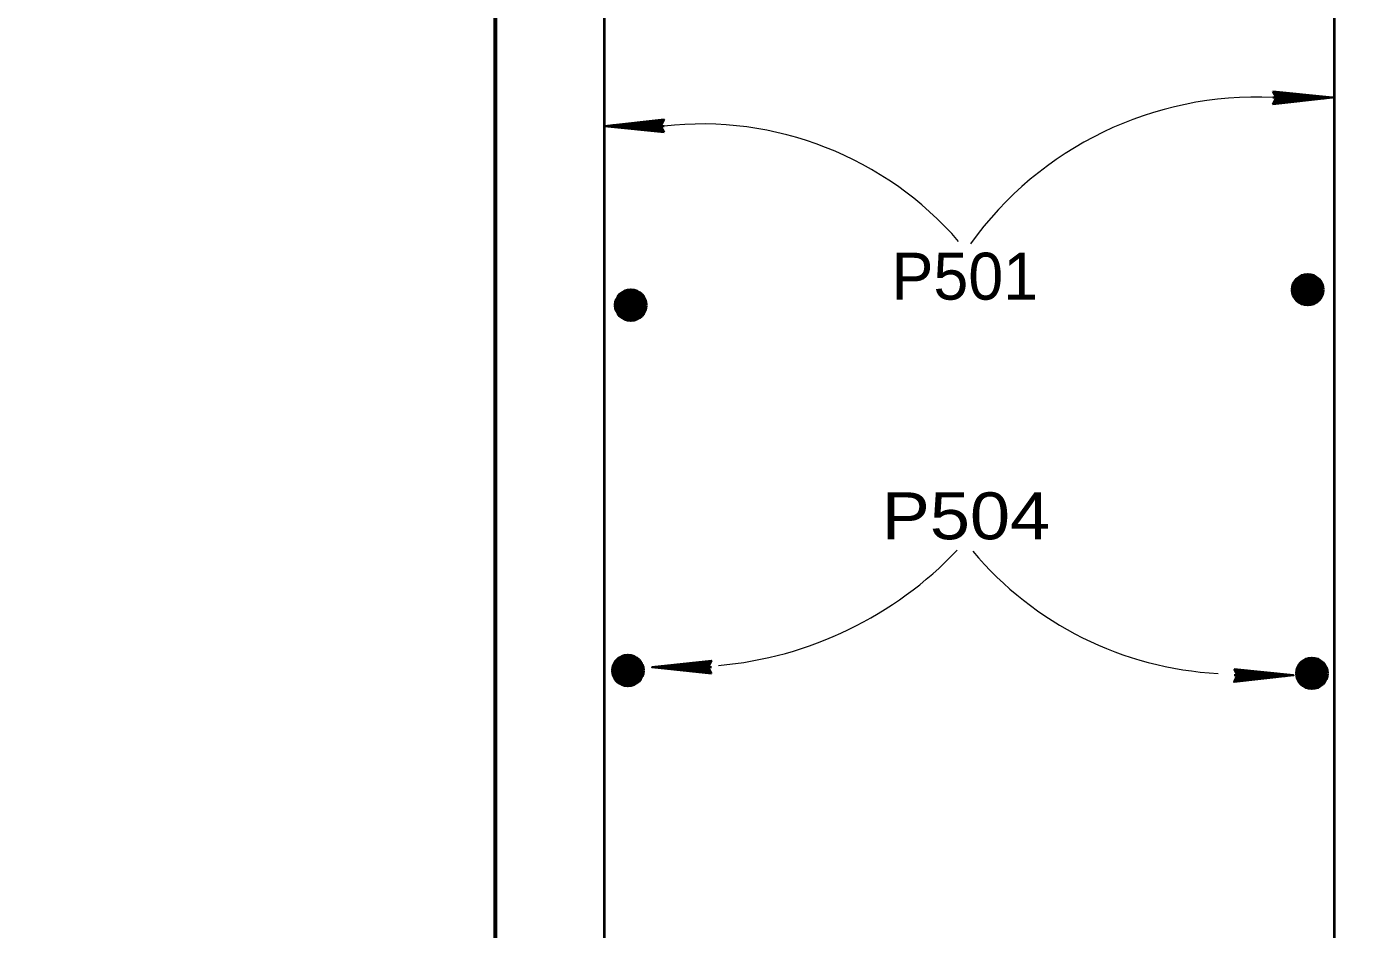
# Model space of a CAD drawing. Extents: x 3.64 to 6.84, y -0.8 to 1.19.
# Drawn here: x 5.0189 to 5.2545, y 0.0313 to 0.1917 of the extents above; entities that cross this region are included whole.
import ezdxf

# ---------------------------------------------------------------- set-up
doc = ezdxf.new("R2010")
doc.units = 0
doc.header["$LTSCALE"] = 0.0033
doc.layers.add('1', color=7, linetype='Continuous', lineweight=40)

msp = doc.modelspace()

# ---------------------------------------------------------------- linework, layer by layer
at = {"layer": '1', "lineweight": 35}
for p, q in [((5.240333, 0.179083), (5.250917, 0.179083)), ((5.2405, 0.178417), (5.247833, 0.179167)), ((5.240583, 0.180083), (5.248417, 0.179167)), ((5.240583, 0.180083), (5.248417, 0.179167)), ((5.240583, 0.18), (5.248417, 0.179167)), ((5.240583, 0.179917), (5.248417, 0.179083)), ((5.240583, 0.179917), (5.248417, 0.178917)), ((5.240583, 0.17825), (5.247917, 0.179083)), ((5.240583, 0.178167), (5.247917, 0.178917)), ((5.240583, 0.178), (5.247917, 0.178833)), ((5.131917, 0.175083), (5.124583, 0.17425)), ((5.131917, 0.174917), (5.124583, 0.174167)), ((5.131917, 0.174833), (5.124583, 0.174)), ((5.132, 0.174667), (5.124667, 0.173917)), ((5.132167, 0.174), (5.121583, 0.174)), ((5.131917, 0.173167), (5.124083, 0.174167)), ((5.131917, 0.173167), (5.124083, 0.174)), ((5.131917, 0.173), (5.124083, 0.173917)), ((5.131917, 0.173), (5.124083, 0.173917)), ((5.131917, 0.173083), (5.124083, 0.173917)), ((5.140583, 0.077833), (5.13, 0.077833)), ((5.140333, 0.077), (5.1325, 0.078)), ((5.140333, 0.077), (5.1325, 0.077833)), ((5.140333, 0.076833), (5.1325, 0.07775)), ((5.140333, 0.076833), (5.1325, 0.07775)), ((5.140333, 0.076917), (5.1325, 0.07775)), ((5.140333, 0.078917), (5.133, 0.078083)), ((5.140333, 0.07875), (5.133, 0.078)), ((5.140333, 0.078667), (5.133, 0.077833)), ((5.140417, 0.0785), (5.133083, 0.07775)), ((5.233417, 0.076417), (5.244, 0.076417)), ((5.233583, 0.07575), (5.240917, 0.0765)), ((5.233667, 0.077417), (5.2415, 0.0765)), ((5.233667, 0.077417), (5.2415, 0.0765)), ((5.233667, 0.077333), (5.2415, 0.0765)), ((5.233667, 0.07725), (5.2415, 0.076417)), ((5.233667, 0.07725), (5.2415, 0.07625)), ((5.233667, 0.075583), (5.241, 0.076417)), ((5.233667, 0.0755), (5.241, 0.07625)), ((5.233667, 0.075333), (5.241, 0.076167))]:
    msp.add_line(p, q, dxfattribs=at)
at = {"layer": '1'}
for p, q in [((5.244417, 0.1465), (5.249, 0.144333)), ((5.244667, 0.146083), (5.248583, 0.145333)), ((5.24475, 0.1465), (5.248667, 0.145833)), ((5.24475, 0.146333), (5.248667, 0.145583)), ((5.244833, 0.146833), (5.248667, 0.146167)), ((5.24675, 0.146), (5.248083, 0.147)), ((5.248833, 0.146167), (5.247583, 0.147333)), ((5.124167, 0.14375), (5.12875, 0.141583)), ((5.1245, 0.14375), (5.128417, 0.143083)), ((5.124583, 0.144083), (5.128417, 0.143417)), ((5.1265, 0.14325), (5.127833, 0.14425)), ((5.128583, 0.143417), (5.127333, 0.144583)), ((5.24425, 0.14375), (5.248083, 0.143)), ((5.244333, 0.14425), (5.24825, 0.1435)), ((5.244333, 0.144083), (5.248167, 0.143333)), ((5.244333, 0.143833), (5.248167, 0.143167)), ((5.244417, 0.144667), (5.248333, 0.143917)), ((5.2445, 0.145083), (5.248333, 0.144333)), ((5.2445, 0.144917), (5.248333, 0.144167)), ((5.244583, 0.1455), (5.248417, 0.144833)), ((5.244583, 0.145333), (5.248417, 0.144583)), ((5.244667, 0.145917), (5.248583, 0.145167)), ((5.244667, 0.145667), (5.2485, 0.144917)), ((5.124083, 0.1415), (5.128, 0.14075)), ((5.124083, 0.141333), (5.127917, 0.140583)), ((5.124167, 0.141917), (5.128083, 0.141167)), ((5.12425, 0.142333), (5.128083, 0.141583)), ((5.12425, 0.142167), (5.128083, 0.141417)), ((5.124333, 0.14275), (5.128167, 0.142083)), ((5.124333, 0.142583), (5.128167, 0.141833)), ((5.124417, 0.143333), (5.128333, 0.142583)), ((5.124417, 0.143167), (5.128333, 0.142417)), ((5.124417, 0.142917), (5.12825, 0.142167)), ((5.1245, 0.143583), (5.128417, 0.142833)), ((5.24425, 0.143583), (5.248083, 0.142833)), ((5.248583, 0.143333), (5.244833, 0.142917)), ((5.124, 0.141), (5.127833, 0.14025)), ((5.124, 0.140833), (5.127833, 0.140083)), ((5.124083, 0.141083), (5.127917, 0.140417)), ((5.128333, 0.140583), (5.124583, 0.140167)), ((5.123667, 0.078833), (5.12825, 0.076667)), ((5.123833, 0.077833), (5.127667, 0.077167)), ((5.123917, 0.078417), (5.127833, 0.077667)), ((5.123917, 0.07825), (5.127833, 0.0775)), ((5.123917, 0.078), (5.12775, 0.07725)), ((5.124, 0.078833), (5.127917, 0.078167)), ((5.124, 0.078667), (5.127917, 0.077917)), ((5.124083, 0.079167), (5.127917, 0.0785)), ((5.126, 0.078333), (5.127333, 0.079333)), ((5.128083, 0.0785), (5.126833, 0.079667)), ((5.245167, 0.078333), (5.24975, 0.076167)), ((5.245417, 0.077917), (5.249333, 0.077167)), ((5.245417, 0.07775), (5.249333, 0.077)), ((5.2455, 0.078333), (5.249417, 0.077667)), ((5.2455, 0.078167), (5.249417, 0.077417)), ((5.245583, 0.078667), (5.249417, 0.078)), ((5.2475, 0.077833), (5.248833, 0.078833)), ((5.249583, 0.078), (5.248333, 0.079167)), ((5.1235, 0.076083), (5.127333, 0.075333)), ((5.1235, 0.075917), (5.127333, 0.075167)), ((5.123583, 0.076583), (5.1275, 0.075833)), ((5.123583, 0.076417), (5.127417, 0.075667)), ((5.123583, 0.076167), (5.127417, 0.0755)), ((5.123667, 0.077), (5.127583, 0.07625)), ((5.12375, 0.077417), (5.127583, 0.076667)), ((5.12375, 0.07725), (5.127583, 0.0765)), ((5.123833, 0.077667), (5.127667, 0.076917)), ((5.127833, 0.075667), (5.124083, 0.07525)), ((5.245, 0.075583), (5.248833, 0.074833)), ((5.245, 0.075417), (5.248833, 0.074667)), ((5.245083, 0.076083), (5.249, 0.075333)), ((5.245083, 0.075917), (5.248917, 0.075167)), ((5.245083, 0.075667), (5.248917, 0.075)), ((5.245167, 0.0765), (5.249083, 0.07575)), ((5.24525, 0.076917), (5.249083, 0.076167)), ((5.24525, 0.07675), (5.249083, 0.076)), ((5.245333, 0.077333), (5.249167, 0.076667)), ((5.245333, 0.077167), (5.249167, 0.076417)), ((5.245417, 0.0775), (5.24925, 0.07675)), ((5.249333, 0.075167), (5.245583, 0.07475))]:
    msp.add_line(p, q, dxfattribs=at)
at = {"layer": '1', "lineweight": 60}
for p, q in [((5.244667, 0.1465), (5.2445, 0.143583)), ((5.244917, 0.1465), (5.244667, 0.143583)), ((5.245083, 0.1465), (5.244917, 0.1435)), ((5.24525, 0.1465), (5.245, 0.1435)), ((5.245417, 0.1465), (5.24525, 0.1435)), ((5.245667, 0.1465), (5.2455, 0.1435)), ((5.245917, 0.1465), (5.245667, 0.1435)), ((5.246, 0.146417), (5.245833, 0.1435)), ((5.246167, 0.146417), (5.246, 0.1435)), ((5.246333, 0.146417), (5.246167, 0.1435)), ((5.246583, 0.146417), (5.246333, 0.1435)), ((5.24675, 0.146417), (5.246583, 0.1435)), ((5.247, 0.146333), (5.24675, 0.143417)), ((5.24725, 0.146333), (5.247, 0.143417)), ((5.247417, 0.146333), (5.24725, 0.143417)), ((5.2475, 0.146333), (5.247333, 0.143417)), ((5.247667, 0.146333), (5.2475, 0.143417)), ((5.24775, 0.146333), (5.247583, 0.143417)), ((5.248, 0.14625), (5.24775, 0.143333)), ((5.248167, 0.14625), (5.248, 0.143333)), ((5.248333, 0.14625), (5.248083, 0.143333)), ((5.2485, 0.14625), (5.248333, 0.143333)), ((5.24875, 0.14625), (5.248583, 0.143333)), ((5.249, 0.144333), (5.248833, 0.146167)), ((5.124417, 0.14375), (5.12425, 0.140833)), ((5.124667, 0.14375), (5.124417, 0.140833)), ((5.124833, 0.14375), (5.124667, 0.14075)), ((5.125, 0.14375), (5.12475, 0.14075)), ((5.125167, 0.14375), (5.125, 0.14075)), ((5.125417, 0.14375), (5.12525, 0.14075)), ((5.125667, 0.14375), (5.125417, 0.14075)), ((5.249, 0.144333), (5.24425, 0.143583)), ((5.12875, 0.141583), (5.124, 0.140833)), ((5.12575, 0.143667), (5.125583, 0.14075)), ((5.125917, 0.143667), (5.12575, 0.14075)), ((5.126083, 0.143667), (5.125917, 0.14075)), ((5.126333, 0.143667), (5.126083, 0.14075)), ((5.1265, 0.143667), (5.126333, 0.14075)), ((5.12675, 0.143583), (5.1265, 0.140667)), ((5.127, 0.143583), (5.12675, 0.140667)), ((5.127167, 0.143583), (5.127, 0.140667)), ((5.12725, 0.143583), (5.127083, 0.140667)), ((5.127417, 0.143583), (5.12725, 0.140667)), ((5.1275, 0.143583), (5.127333, 0.140667)), ((5.12775, 0.1435), (5.1275, 0.140583)), ((5.127917, 0.1435), (5.12775, 0.140583)), ((5.128083, 0.1435), (5.127833, 0.140583)), ((5.12825, 0.1435), (5.128083, 0.140583)), ((5.1285, 0.1435), (5.128333, 0.140583)), ((5.12875, 0.141583), (5.128583, 0.143417)), ((5.123917, 0.078833), (5.12375, 0.075917)), ((5.124167, 0.078833), (5.123917, 0.075917)), ((5.124333, 0.078833), (5.124167, 0.075833)), ((5.1245, 0.078833), (5.12425, 0.075833)), ((5.124667, 0.078833), (5.1245, 0.075833)), ((5.124917, 0.078833), (5.12475, 0.075833)), ((5.125167, 0.078833), (5.124917, 0.075833)), ((5.12525, 0.07875), (5.125083, 0.075833)), ((5.125417, 0.07875), (5.12525, 0.075833)), ((5.125583, 0.07875), (5.125417, 0.075833)), ((5.125833, 0.07875), (5.125583, 0.075833)), ((5.126, 0.07875), (5.125833, 0.075833)), ((5.12625, 0.078667), (5.126, 0.07575)), ((5.1265, 0.078667), (5.12625, 0.07575)), ((5.126667, 0.078667), (5.1265, 0.07575)), ((5.12675, 0.078667), (5.126583, 0.07575)), ((5.126917, 0.078667), (5.12675, 0.07575)), ((5.127, 0.078667), (5.126833, 0.07575)), ((5.12725, 0.078583), (5.127, 0.075667)), ((5.127417, 0.078583), (5.12725, 0.075667)), ((5.127583, 0.078583), (5.127333, 0.075667)), ((5.12775, 0.078583), (5.127583, 0.075667)), ((5.128, 0.078583), (5.127833, 0.075667)), ((5.12825, 0.076667), (5.128083, 0.0785)), ((5.245417, 0.078333), (5.24525, 0.075417)), ((5.245667, 0.078333), (5.245417, 0.075417)), ((5.245833, 0.078333), (5.245667, 0.075333)), ((5.246, 0.078333), (5.24575, 0.075333)), ((5.246167, 0.078333), (5.246, 0.075333)), ((5.246417, 0.078333), (5.24625, 0.075333)), ((5.246667, 0.078333), (5.246417, 0.075333)), ((5.24675, 0.07825), (5.246583, 0.075333)), ((5.246917, 0.07825), (5.24675, 0.075333)), ((5.247083, 0.07825), (5.246917, 0.075333)), ((5.247333, 0.07825), (5.247083, 0.075333)), ((5.2475, 0.07825), (5.247333, 0.075333)), ((5.24775, 0.078167), (5.2475, 0.07525)), ((5.248, 0.078167), (5.24775, 0.07525)), ((5.248167, 0.078167), (5.248, 0.07525)), ((5.24825, 0.078167), (5.248083, 0.07525)), ((5.248417, 0.078167), (5.24825, 0.07525)), ((5.2485, 0.078167), (5.248333, 0.07525)), ((5.24875, 0.078083), (5.2485, 0.075167)), ((5.248917, 0.078083), (5.24875, 0.075167)), ((5.249083, 0.078083), (5.248833, 0.075167)), ((5.24925, 0.078083), (5.249083, 0.075167)), ((5.2495, 0.078083), (5.249333, 0.075167)), ((5.24975, 0.076167), (5.249583, 0.078)), ((5.12825, 0.076667), (5.1235, 0.075917)), ((5.24975, 0.076167), (5.245, 0.075417))]:
    msp.add_line(p, q, dxfattribs=at)
for points in [[(5.018917, -0.058667), (5.10225, -0.058667), (5.10225, 0.274667), (5.268917, 0.274667), (5.268917, -0.058667), (5.35225, -0.058667)], [(5.243833, 0.144833), (5.249, 0.1455), (5.244417, 0.1465)], [(5.248083, 0.142833), (5.248083, 0.147), (5.246417, 0.142333), (5.246917, 0.1475), (5.244833, 0.142917), (5.245583, 0.147417), (5.247167, 0.142417), (5.244, 0.14575), (5.248833, 0.146167), (5.245583, 0.1425), (5.247583, 0.147333), (5.244417, 0.1465), (5.24425, 0.143583)], [(5.244833, 0.142917), (5.246333, 0.145167), (5.244167, 0.146083), (5.246167, 0.1475), (5.246333, 0.14525), (5.248, 0.142917), (5.244, 0.14525), (5.24675, 0.146)], [(5.247583, 0.147333), (5.246333, 0.145167), (5.248583, 0.143333)], [(5.123583, 0.142083), (5.12875, 0.14275), (5.124167, 0.14375)], [(5.127833, 0.140083), (5.127833, 0.14425), (5.126167, 0.139583), (5.126667, 0.14475), (5.124583, 0.140167), (5.125333, 0.144667), (5.126917, 0.139667), (5.12375, 0.143), (5.128583, 0.143417), (5.125333, 0.13975), (5.127333, 0.144583), (5.124167, 0.14375), (5.124, 0.140833)], [(5.124583, 0.140167), (5.126083, 0.142417), (5.123917, 0.143333), (5.125917, 0.14475), (5.126083, 0.1425), (5.12775, 0.140167), (5.12375, 0.1425), (5.1265, 0.14325)], [(5.127333, 0.144583), (5.126083, 0.142417), (5.128333, 0.140583)], [(5.123083, 0.077167), (5.12825, 0.077833), (5.123667, 0.078833)], [(5.127333, 0.075167), (5.127333, 0.079333), (5.125667, 0.074667), (5.126167, 0.079833), (5.124083, 0.07525), (5.124833, 0.07975), (5.126417, 0.07475), (5.12325, 0.078083), (5.128083, 0.0785), (5.124833, 0.074833), (5.126833, 0.079667), (5.123667, 0.078833), (5.1235, 0.075917)], [(5.124083, 0.07525), (5.125583, 0.0775), (5.123417, 0.078417), (5.125417, 0.079833), (5.125583, 0.077583), (5.12725, 0.07525), (5.12325, 0.077583), (5.126, 0.078333)], [(5.126833, 0.079667), (5.125583, 0.0775), (5.127833, 0.075667)], [(5.244583, 0.076667), (5.24975, 0.077333), (5.245167, 0.078333)], [(5.248833, 0.074667), (5.248833, 0.078833), (5.247167, 0.074167), (5.247667, 0.079333), (5.245583, 0.07475), (5.246333, 0.07925), (5.247917, 0.07425), (5.24475, 0.077583), (5.249583, 0.078), (5.246333, 0.074333), (5.248333, 0.079167), (5.245167, 0.078333), (5.245, 0.075417)], [(5.245583, 0.07475), (5.247083, 0.077), (5.244917, 0.077917), (5.246917, 0.079333), (5.247083, 0.077083), (5.24875, 0.07475), (5.24475, 0.077083), (5.2475, 0.077833)], [(5.248333, 0.079167), (5.247083, 0.077), (5.249333, 0.075167)]]:
    msp.add_lwpolyline(points, dxfattribs=at)
at = {"layer": '1'}
for points in [[(5.127417, 0.254), (5.127417, 0.205333), (5.1215, 0.199417), (5.1215, -0.008917), (5.127417, -0.014833), (5.127417, -0.04725)], [(5.245333, -0.044), (5.245333, -0.014917), (5.25125, -0.009), (5.25125, 0.199333), (5.245333, 0.20525), (5.245333, 0.253833)], [(5.24425, 0.143583), (5.246333, 0.142333), (5.248083, 0.142833), (5.249, 0.144333)], [(5.124, 0.140833), (5.126083, 0.139583), (5.127833, 0.140083), (5.12875, 0.141583)], [(5.1235, 0.075917), (5.125583, 0.074667), (5.127333, 0.075167), (5.12825, 0.076667)], [(5.245, 0.075417), (5.247083, 0.074167), (5.248833, 0.074667), (5.24975, 0.076167)]]:
    msp.add_lwpolyline(points, dxfattribs=at)
at = {"layer": '1', "lineweight": 35}
for points in [[(5.240333, 0.180167), (5.250917, 0.179083), (5.240333, 0.177917), (5.240917, 0.179083)], [(5.241083, 0.179167), (5.24575, 0.17925), (5.24575, 0.179167), (5.244833, 0.179167), (5.241083, 0.17925), (5.244083, 0.179333), (5.240917, 0.179417), (5.243167, 0.1795), (5.240917, 0.179583), (5.244417, 0.179333), (5.249083, 0.179167), (5.248167, 0.178917), (5.249417, 0.178917), (5.241083, 0.178917), (5.2435, 0.17875), (5.240917, 0.17875), (5.24625, 0.179167), (5.240917, 0.1785)], [(5.132167, 0.172917), (5.121583, 0.174), (5.132167, 0.175167), (5.131583, 0.174)], [(5.131417, 0.173917), (5.12675, 0.173833), (5.12675, 0.173917), (5.127667, 0.173917), (5.131417, 0.173833), (5.128417, 0.17375), (5.131583, 0.173667), (5.129333, 0.173583), (5.131583, 0.1735), (5.128083, 0.17375), (5.123417, 0.173917), (5.124333, 0.174167), (5.123083, 0.174167), (5.131417, 0.174167), (5.129, 0.174333), (5.131583, 0.174333), (5.12625, 0.173917), (5.131583, 0.174583)], [(5.140583, 0.07675), (5.13, 0.077833), (5.140583, 0.079), (5.14, 0.077833)], [(5.139833, 0.07775), (5.135167, 0.077667), (5.135167, 0.07775), (5.136083, 0.07775), (5.139833, 0.077667), (5.136833, 0.077583), (5.14, 0.0775), (5.13775, 0.077417), (5.14, 0.077333), (5.1365, 0.077583), (5.131833, 0.07775), (5.13275, 0.078), (5.1315, 0.078), (5.139833, 0.078), (5.137417, 0.078167), (5.14, 0.078167), (5.134667, 0.07775), (5.14, 0.078417)], [(5.233417, 0.0775), (5.244, 0.076417), (5.233417, 0.07525), (5.234, 0.076417)], [(5.234167, 0.0765), (5.238833, 0.076583), (5.238833, 0.0765), (5.237917, 0.0765), (5.234167, 0.076583), (5.237167, 0.076667), (5.234, 0.07675), (5.23625, 0.076833), (5.234, 0.076917), (5.2375, 0.076667), (5.242167, 0.0765), (5.24125, 0.07625), (5.2425, 0.07625), (5.234167, 0.07625), (5.236583, 0.076083), (5.234, 0.076083), (5.239333, 0.0765), (5.234, 0.075833)]]:
    msp.add_lwpolyline(points, close=True, dxfattribs=at)
for points in [[(5.241083, 0.179167), (5.240667, 0.179917), (5.240917, 0.179667), (5.241083, 0.179333), (5.241333, 0.179417), (5.241167, 0.17975), (5.241, 0.179), (5.240833, 0.1785), (5.240583, 0.178083)], [(5.131417, 0.173917), (5.131833, 0.173167), (5.131583, 0.173417), (5.131417, 0.17375), (5.131167, 0.173667), (5.131333, 0.173333), (5.1315, 0.174083), (5.131667, 0.174583), (5.131917, 0.175)], [(5.139833, 0.07775), (5.14025, 0.077), (5.14, 0.07725), (5.139833, 0.077583), (5.139583, 0.0775), (5.13975, 0.077167), (5.139917, 0.077917), (5.140083, 0.078417), (5.140333, 0.078833)], [(5.234167, 0.0765), (5.23375, 0.07725), (5.234, 0.077), (5.234167, 0.076667), (5.234417, 0.07675), (5.23425, 0.077083), (5.234083, 0.076333), (5.233917, 0.075833), (5.233667, 0.075417)]]:
    msp.add_lwpolyline(points, dxfattribs=at)
at = {"layer": '1', "lineweight": 60}
for centre in [(5.2465, 0.144933), (5.12625, 0.142183), (5.12575, 0.077267), (5.24725, 0.076767)]:
    msp.add_circle(centre, 0.00264, dxfattribs=at)
at = {"layer": '1', "lineweight": 13}
for centre, radius, start, end in [((5.237389, 0.116611), 0.062542, 87.30189, 144.32616), ((5.138881, 0.11409), 0.060285, 40.82327, 96.39421), ((5.136046, 0.144274), 0.06636, 275.00335, 316.58566), ((5.233797, 0.137732), 0.061067, 219.97438, 266.98319)]:
    msp.add_arc(centre, radius, start, end, dxfattribs=at)

# ---------------------------------------------------------------- texts
at = {"layer": '1'}
msp.add_text('P501', height=0.008333, dxfattribs=at).set_placement((5.172583, 0.143167))
at = {"layer": '1', "width": 1.15}
msp.add_text('P504', height=0.008333, dxfattribs=at).set_placement((5.170833, 0.100583))

doc.saveas('drawing.dxf')
